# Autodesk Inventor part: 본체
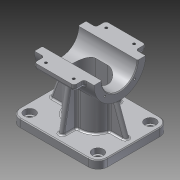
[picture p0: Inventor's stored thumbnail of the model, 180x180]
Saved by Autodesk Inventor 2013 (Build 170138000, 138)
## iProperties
Company: 한국ATC센터
Created: 2014-02
Part Number: 본체
Document SubType Name: Modeling
Designer: KYOUNG IL JANG
Density: 2.71 g/cm^3
Material: 알루미늄-6061
Vendor: CBT Solutions
Author: KYOUNG IL JANG
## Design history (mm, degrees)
sketch "스케치1"
  geometry: L1 (-55, 45)-(55, 45); L2 (55, 45)-(55, -45); L3 (55, -45)-(-55, -45); L4 (-55, -45)-(-55, 45); 3 further points
  constraints: 8 end point, 2 midpoint, 2 parallel, 1 horizontal, 1 horizontal alignment, 1 perpendicular, 1 vertical alignment
  dimensions: "d0" = 110 distance of L2.end L3.end; "d1" = 90 distance of L1.end L2.end
extrude "돌출1" new body sketch "스케치1" distance "d2" = 10; taper "d3" = 0 deg
sketch "스케치2"
  geometry: L1 (45, 0)-(-45, 0) reference; C1 r 32.5 at (0, 80); 2 further points
  constraints: 1 centre point, 1 midpoint, 1 vertical alignment
  dimensions: "d4" = 65 diameter of C1; "d5" = 80 distance from line of C1.centre L1
extrude "돌출2" join sketch "스케치2" stored distance "d6" = 75; taper "d7" = 0 deg
sketch "스케치3"
  geometry: L1 (-7.5, -20)-(7.5, -20); L2 (7.5, 20)-(-7.5, 20); A1 r 20 centre (7.5, 0) between (7.5, -20) and (7.5, 20); A2 r 20 centre (-7.5, 0) between (-7.5, 20) and (-7.5, -20); 2 further points
  constraints: 4 end point, 4 point on circle, 4 tangent, 2 centre point, 1 horizontal, 1 horizontal alignment, 1 midpoint, 1 parallel, 1 vertical alignment
  dimensions: "d8" = 20 radius of A2; "d9" = 55 dimension on A1 A2
extrude "돌출3" join sketch "스케치3" stored distance "d10" = 75; taper "d11" = 0 deg
fillet "모깎기1" dims "d12" = 12
sketch "스케치4"
  geometry: L1 (-55, 0)-(-55, 10) reference; L2 (37.5, 47.5)-(-37.5, 47.5) reference; L3 (-48, 10)-(-34.351, 47.5); 1 further point
  constraints: 2 end point, 1 horizontal alignment, 1 point on line
  dimensions: "d105" = 7 distance from line of L3.start L1; "d106" = 110 deg dimension on L3.start L3.end L1.end
sketch "스케치5"
  geometry: L1 (-45, 0)-(-45, 10) reference; L2 (-38, 10)-(-28.433, 64.258); 2 further points
  constraints: 2 end point, 1 horizontal alignment, 2 other
  dimensions: "d107" = 7 distance from line of L2.start L1; "d108" = 100 deg dimension on L2.start L2.end L1.end
feature "리브1" dims "d15" = 1, "d16" = 6, "d17" = 0
feature "리브2" dims "d18" = 1, "d19" = 6, "d20" = 0
fillet "모깎기3" dims "d22" = 3
fillet "모깎기4" dims "d23" = 3
fillet "모깎기5" dims "d24" = 3
fillet "모깎기6" dims "d25" = 3
fillet "모깎기7" dims "d26" = 3
fillet "모깎기12" dims "d109" = 2
sketch "스케치6"
  geometry: A1 r 12 centre (43, -33) between (43, -45) and (55, -33) reference; A2 r 12 centre (-43, -33) between (-55, -33) and (-43, -45) reference; A3 r 12 centre (-43, 33) between (-43, 45) and (-55, 33) reference; A4 r 12 centre (43, 33) between (55, 33) and (43, 45) reference; 1 further point
hole "구멍7" sketch "스케치6" at (43, -33), (-43, -33), (-43, 33), (43, 33) diameter "d110" = 9; stored, may be unused: countersink angle "d114" = 90 deg, drill point angle "d116" = 118 deg; dims "d111" = 6, "d112" = 14, "d113" = 6.6, "d115" = 8
hole "구멍2" diameter "d37" = 45; stored, may be unused: countersink angle "d41" = 90 deg, drill point angle "d43" = 118 deg; dims "d35" = 10, "d36" = 10, "d38" = 6, "d39" = 4, "d40" = 2, "d42" = 8
sketch "스케치7"
  geometry: C1 r 22.5 at (0, 0) reference; 2 further points
  dimensions: "d44" = 135 deg dimension on C1.centre point (-18.738, 18.738) point (80, 0); "d45" = 26.5 distance of point (-18.738, 18.738) C1.centre
hole "구멍3" sketch "스케치7" at (-18.738, 18.738) diameter "d46" = 2.459; stored, may be unused: countersink angle "d50" = 90 deg, drill point angle "d52" = 118 deg; dims "d47" = 8, "d48" = 4, "d49" = 2, "d51" = 10
node "작업 평면1"
sketch "스케치8"
  geometry: C1 r 10 at (0, 0); 1 further point
  constraints: 1 centre point, 1 coincident
  dimensions: "d57" = 20 diameter of C1
extrude "돌출4" join sketch "스케치8" stored distance "d58" = 75; taper "d59" = 0 deg
hole "구멍4" diameter "d62" = 8.376; stored, may be unused: countersink angle "d66" = 90 deg, drill point angle "d68" = 118 deg; dims "d60" = 10, "d61" = 10, "d63" = 7, "d64" = 4, "d65" = 2, "d67" = 10
chamfer "모따기1" distance "d69" = 1; stored, may be unused: second distance "d70" = 2, angle "d71" = 45 deg
fillet "모깎기9" dims "d72" = 3
sketch "스케치9"
  geometry: L1 (-31.623, 87.5)-(-45, 87.5); L2 (-45, 87.5)-(-45, 72.5); L3 (-45, 72.5)-(-31.623, 72.5); A1 r 32.5 centre (0, 80) between (-31.623, 87.5) and (-31.623, 72.5) reference; 1 further point
  constraints: 6 end point, 2 parallel, 2 point on circle, 1 horizontal, 1 perpendicular
  dimensions: "d73" = 15 distance of L1.end L2.end; "d74" = 45 distance from line of A1.centre L2
extrude "돌출5" join sketch "스케치9" stored distance "d75" = 50; taper "d76" = 0 deg
fillet "모깎기10" dims "d77" = 3
fillet "모깎기11" dims "d78" = 3
sketch "스케치10"
  geometry: L1 (-61.625, 62.366)-(0, 62.366); L2 (0, 62.366)-(0, -62.366); L3 (0, -62.366)-(-61.625, -62.366); L4 (-61.625, -62.366)-(-61.625, 62.366); C1 r 32.5 at (0, 0) reference; 2 further points
  constraints: 8 end point, 2 parallel, 1 coincident, 1 horizontal, 1 midpoint, 1 perpendicular
extrude "돌출6" cut sketch "스케치10" stored distance "d79" = 10; taper "d80" = 0 deg
node "작업 평면2"
sketch "스케치11"
  geometry: L1 (-7.5, -15)-(7.5, -15); L2 (7.5, 15)-(-7.5, 15); A1 r 15 centre (7.5, 0) between (7.5, -15) and (7.5, 15); A2 r 15 centre (-7.5, 0) between (-7.5, 15) and (-7.5, -15); 2 further points
  constraints: 4 end point, 4 point on circle, 4 tangent, 2 centre point, 1 horizontal, 1 horizontal alignment, 1 midpoint, 1 parallel, 1 vertical alignment
  dimensions: "d82" = 15 radius of A2; "d117" = 45 dimension on A2 A1
extrude "돌출7" cut sketch "스케치11" stored distance "d83" = 10; taper "d84" = 0 deg
sketch "스케치12"
  geometry: 1 further point
hole "구멍5" sketch "스케치12" at (0, 0) diameter "d85" = 12; stored, may be unused: countersink angle "d89" = 90 deg, drill point angle "d91" = 118 deg; dims "d86" = 6, "d87" = 38, "d88" = 10, "d90" = 8
sketch "스케치13"
  geometry: L1 (-15.5, -12.5)-(-59.5, -12.5) reference; 3 further points
  constraints: 1 horizontal alignment
  dimensions: "d92" = 35 distance of point (-20, -5.5) point (-55, -5.5); "d93" = 17.5 horizontal distance of point (-37.5, 32.5) point (-55, -5.5) (= 0.5 x d92); "d94" = 7 distance from line of L1 point (-55, -5.5)
hole "구멍6" sketch "스케치13" at (-55, -5.5), (-20, -5.5) diameter "d95" = 3.242; stored, may be unused: countersink angle "d99" = 90 deg, drill point angle "d101" = 118 deg; dims "d96" = 6, "d97" = 38, "d98" = 10, "d100" = 8
sketch "스케치14"
  geometry: C1 r 10 at (0, 0); 1 further point
  constraints: 1 centre point, 1 coincident
  dimensions: "d102" = 20 diameter of C1
extrude "돌출8" cut sketch "스케치14" distance "d103" = 5; taper "d104" = 0 deg
chamfer "모따기2" distance "d118" = 1; stored, may be unused: second distance "d119" = 2, angle "d120" = 45 deg
node "솔리드1"
mirror "대칭1"
mirror "대칭2"
pattern_circular "원형 패턴1" dims angle "d54" = 360 deg
mirror "대칭5"
mirror "대칭6"
mirror "대칭7"
other parameters: "d56" = -117
